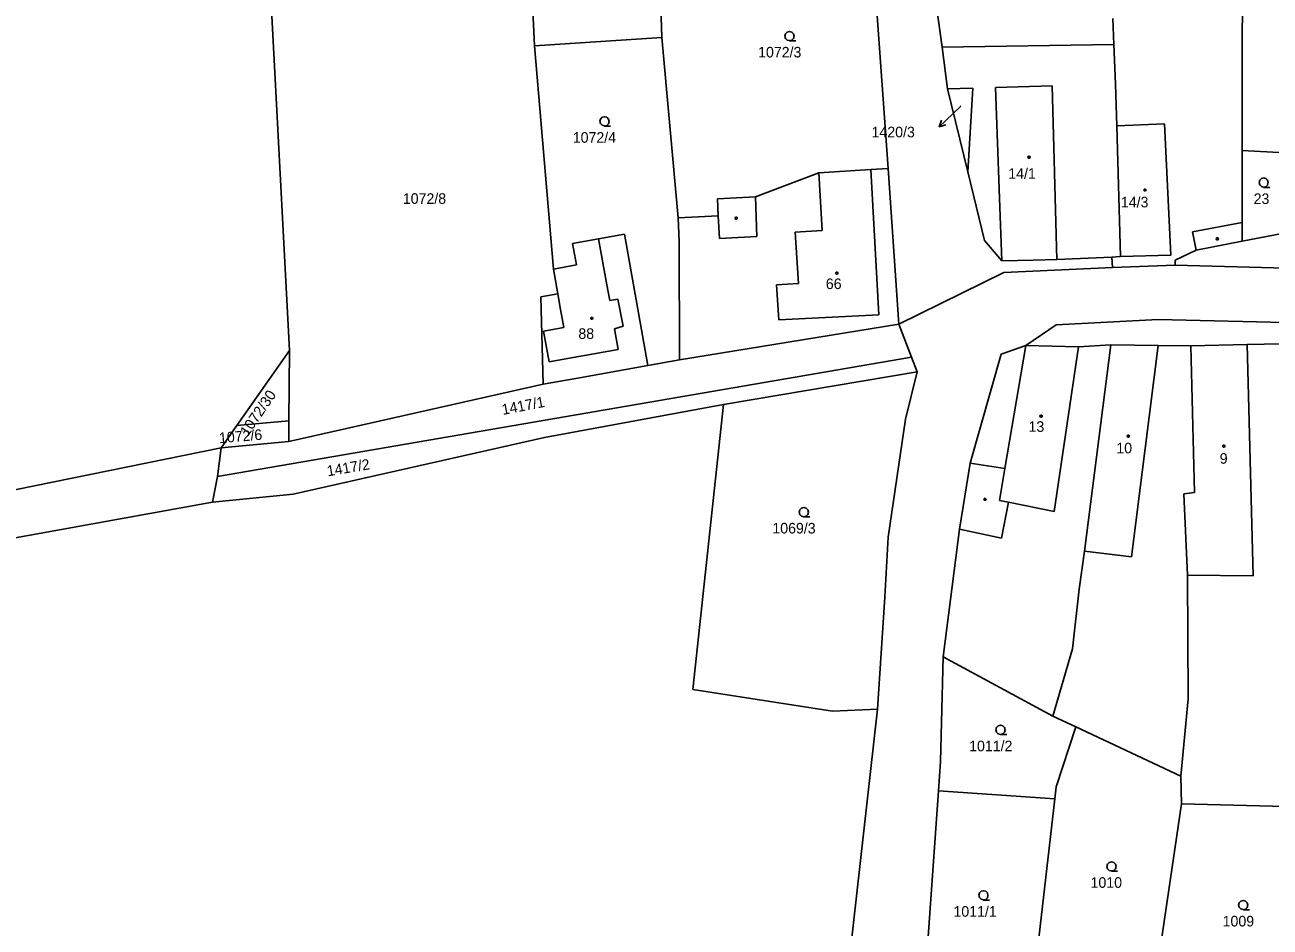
# Model space of a CAD drawing. Extents: x -850689 to -847910, y -1058374 to -1054747.
# Drawn here: x -849716.8 to -849516.8, y -1056444.2 to -1056299.3 of the extents above; entities that cross this region are included whole.
import ezdxf

# ---------------------------------------------------------------- set-up
doc = ezdxf.new("R2010")
doc.units = 0
for name, color, linetype in [('KN_HRANICE', 7, 'Continuous'), ('KN_KULTURY', 7, 'Continuous'), ('KN_PARCELY', 7, 'Continuous'), ('KN_SLUCKY', 7, 'Continuous'), ('KN_STAVEBNI', 7, 'Continuous')]:
    doc.layers.add(name, color=color, linetype=linetype)

# ---------------------------------------------------------------- blocks, each defined once
blk = doc.blocks.new('304')
blk.add_lwpolyline([(0, 0), (-0.38, 0.1), (-0.65, 0.37), (-0.75, 0.74), (-0.65, 1.11), (-0.38, 1.38), (-0.01, 1.48), (0.36, 1.38), (0.63, 1.11), (0.73, 0.73), (0.63, 0.35), (0.36, 0.08), (-0.02, -0.02), (0.98, -0.02)])
blk = doc.blocks.new('10292')
blk.add_line((0, 3), (0, 0))
blk.add_lwpolyline([(-0.5, 2), (0, 3), (0.5, 2)])
blk = doc.blocks.new('402')
blk.add_lwpolyline([(0.09, 0.15), (0.18, 0), (0.09, -0.15), (-0.09, -0.15), (-0.18, 0), (-0.09, 0.15), (0.09, 0.15)])

msp = doc.modelspace()

# ---------------------------------------------------------------- linework, layer by layer
at = {"layer": 'KN_HRANICE'}
for p, q in [((-849614.51, -1056301.38), (-849615.36, -1056276.4)), ((-849572.59, -1056279.79), (-849569.5, -1056302.91)), ((-849674.3, -1056351.59), (-849678, -1056281.13)), ((-849578.15, -1056322.42), (-849580.33, -1056292.14)), ((-849634.92, -1056302.69), (-849635.4, -1056293.21)), ((-849541.91, -1056302.5), (-849542.09, -1056298.32)), ((-849521.32, -1056300.37), (-849521.24, -1056297.73)), ((-849521.32, -1056319.52), (-849521.32, -1056300.37)), ((-849634.92, -1056302.69), (-849614.51, -1056301.38)), ((-849611.88, -1056330.31), (-849614.51, -1056301.38)), ((-849569.5, -1056302.91), (-849541.91, -1056302.5)), ((-849541.64, -1056308.88), (-849541.91, -1056302.5)), ((-849631.91, -1056338.54), (-849634.92, -1056302.69)), ((-849569.5, -1056302.91), (-849568.61, -1056309.6)), ((-849568.61, -1056309.6), (-849564.57, -1056309.49)), ((-849568.61, -1056309.6), (-849565.38, -1056322.92)), ((-849565.38, -1056322.92), (-849564.57, -1056309.49)), ((-849541.64, -1056308.88), (-849541.45, -1056315.57)), ((-849541.45, -1056315.57), (-849540.85, -1056336.53)), ((-849521.32, -1056331.05), (-849521.32, -1056319.52)), ((-849512.43, -1056319.98), (-849521.32, -1056319.52)), ((-849580.93, -1056322.58), (-849589.28, -1056323.07)), ((-849578.15, -1056322.42), (-849580.93, -1056322.58)), ((-849576.45, -1056347.39), (-849578.15, -1056322.42)), ((-849589.28, -1056323.07), (-849599.48, -1056326.92)), ((-849565.38, -1056322.92), (-849562.7, -1056333.97)), ((-849605.58, -1056327.27), (-849599.48, -1056326.92)), ((-849605.43, -1056329.98), (-849605.58, -1056327.27)), ((-849611.88, -1056330.31), (-849605.43, -1056329.98)), ((-849611.73, -1056334.13), (-849611.88, -1056330.31)), ((-849521.3, -1056334.07), (-849521.32, -1056331.05)), ((-849624.66, -1056333.71), (-849628.83, -1056334.46)), ((-849628.83, -1056334.46), (-849628.22, -1056337.88)), ((-849620.5, -1056332.96), (-849624.66, -1056333.71)), ((-849616.72, -1056354), (-849620.5, -1056332.96)), ((-849611.73, -1056334.13), (-849611.68, -1056353.09)), ((-849559.9, -1056337.24), (-849562.7, -1056333.97)), ((-849521.3, -1056334.07), (-849528.68, -1056335.48)), ((-849514.89, -1056332.85), (-849521.3, -1056334.07)), ((-849551.04, -1056336.99), (-849542.24, -1056336.61)), ((-849542.24, -1056336.61), (-849540.85, -1056336.53)), ((-849542.24, -1056336.61), (-849542.14, -1056338.3)), ((-849532.07, -1056337.11), (-849528.68, -1056335.48)), ((-849628.22, -1056337.88), (-849631.91, -1056338.54)), ((-849631.91, -1056338.54), (-849631.2, -1056342.49)), ((-849554.88, -1056337.1), (-849559.9, -1056337.24)), ((-849559.57, -1056339.1), (-849542.14, -1056338.3)), ((-849551.04, -1056336.99), (-849554.88, -1056337.1)), ((-849542.14, -1056338.3), (-849532.06, -1056337.93)), ((-849532.07, -1056337.11), (-849532.06, -1056337.93)), ((-849406.11, -1056341.28), (-849532.06, -1056337.93)), ((-849576.45, -1056347.39), (-849559.57, -1056339.1)), ((-849633.92, -1056342.98), (-849631.2, -1056342.49)), ((-849633.92, -1056342.98), (-849633.57, -1056357.04)), ((-849534.81, -1056346.62), (-849551.16, -1056347.5)), ((-849534.81, -1056346.62), (-849457.69, -1056348.54)), ((-849611.68, -1056353.09), (-849576.45, -1056347.39)), ((-849576.45, -1056347.39), (-849574.4, -1056352.7)), ((-849556.04, -1056350.8), (-849551.16, -1056347.5)), ((-849520.48, -1056350.65), (-849500.05, -1056350.21)), ((-849682.76, -1056363.66), (-849674.3, -1056351.59)), ((-849674.39, -1056362.91), (-849674.3, -1056351.59)), ((-849564.99, -1056369.69), (-849560.02, -1056352.2)), ((-849560.02, -1056352.2), (-849556.04, -1056350.8)), ((-849556.04, -1056350.8), (-849547.59, -1056351.01)), ((-849547.59, -1056351.01), (-849542.41, -1056350.72)), ((-849546.62, -1056383.82), (-849542.41, -1056350.72)), ((-849542.41, -1056350.72), (-849534.78, -1056350.83)), ((-849534.78, -1056350.83), (-849529.54, -1056350.88)), ((-849529.54, -1056350.88), (-849520.48, -1056350.65)), ((-849529.54, -1056350.88), (-849528.97, -1056374.41)), ((-849685.84, -1056371.84), (-849574.4, -1056352.7)), ((-849628.29, -1056356.09), (-849616.72, -1056354)), ((-849616.72, -1056354), (-849611.68, -1056353.09)), ((-849574.4, -1056352.7), (-849573.5, -1056355.04)), ((-849633.57, -1056357.04), (-849628.29, -1056356.09)), ((-849573.5, -1056355.04), (-849604.58, -1056360.3)), ((-849573.5, -1056355.04), (-849575.39, -1056362.66)), ((-849674.41, -1056366.2), (-849633.57, -1056357.04)), ((-849633.36, -1056365.59), (-849604.58, -1056360.3)), ((-849604.58, -1056360.3), (-849609.54, -1056406.05)), ((-849685.27, -1056367.24), (-849682.76, -1056363.66)), ((-849682.76, -1056363.66), (-849674.39, -1056362.91)), ((-849674.41, -1056366.2), (-849674.39, -1056362.91)), ((-849578.13, -1056381.59), (-849575.39, -1056362.66)), ((-849674.41, -1056366.2), (-849685.27, -1056367.24)), ((-849673.7, -1056374.66), (-849633.36, -1056365.59)), ((-849685.27, -1056367.24), (-849734.06, -1056377.17)), ((-849685.27, -1056367.24), (-849685.84, -1056371.84)), ((-849566.68, -1056380.28), (-849564.99, -1056369.69)), ((-849686.68, -1056375.97), (-849685.84, -1056371.84)), ((-849528.97, -1056374.41), (-849530.67, -1056374.61)), ((-849530.67, -1056374.61), (-849530.07, -1056387.67)), ((-849876.14, -1056410.04), (-849686.68, -1056375.97)), ((-849686.68, -1056375.97), (-849673.7, -1056374.66)), ((-849566.68, -1056380.28), (-849569.32, -1056400.81)), ((-849578.69, -1056391.21), (-849578.13, -1056381.59)), ((-849547.5, -1056389.93), (-849546.62, -1056383.82)), ((-849530, -1056407.52), (-849530.07, -1056387.67)), ((-849548.57, -1056399.5), (-849547.5, -1056389.93)), ((-849579.89, -1056409.19), (-849578.69, -1056391.21)), ((-849551.71, -1056410.33), (-849548.57, -1056399.5)), ((-849569.73, -1056417.59), (-849569.32, -1056400.81)), ((-849569.32, -1056400.81), (-849551.71, -1056410.33)), ((-849609.54, -1056406.05), (-849587.11, -1056409.52)), ((-849530, -1056407.52), (-849531.15, -1056419.97)), ((-849587.11, -1056409.52), (-849579.89, -1056409.19)), ((-849585.31, -1056457.89), (-849579.89, -1056409.19)), ((-849551.71, -1056410.33), (-849548.04, -1056412.05)), ((-849551.15, -1056421.68), (-849548.04, -1056412.05)), ((-849548.04, -1056412.05), (-849531.15, -1056419.97)), ((-849570.06, -1056422.29), (-849569.73, -1056417.59)), ((-849531.15, -1056419.97), (-849531.06, -1056424.37)), ((-849572.24, -1056453.32), (-849570.06, -1056422.29)), ((-849551.37, -1056423.56), (-849570.06, -1056422.29)), ((-849551.15, -1056421.68), (-849551.37, -1056423.56)), ((-849551.37, -1056423.56), (-849555.21, -1056456.71)), ((-849531.06, -1056424.37), (-849536.26, -1056459.7)), ((-849507.03, -1056425.02), (-849531.06, -1056424.37))]:
    msp.add_line(p, q, dxfattribs=at)
at = {"layer": 'KN_PARCELY'}
msp.add_line((-849566.46, -1056312.38), (-849567.77, -1056313.63), dxfattribs=at)
at = {"layer": 'KN_SLUCKY'}
for p, q in [((-849560.9, -1056309.39), (-849551.84, -1056309.15)), ((-849560.26, -1056327.16), (-849560.9, -1056309.39)), ((-849551.84, -1056309.15), (-849551.04, -1056336.99)), ((-849541.45, -1056315.57), (-849533.76, -1056315.2)), ((-849532.75, -1056336.3), (-849533.76, -1056315.2)), ((-849579.67, -1056345.88), (-849580.93, -1056322.58)), ((-849589.28, -1056323.07), (-849588.73, -1056332.37)), ((-849599.48, -1056326.92), (-849599.25, -1056333.3)), ((-849559.9, -1056337.24), (-849560.26, -1056327.16)), ((-849605.22, -1056333.64), (-849605.43, -1056329.98)), ((-849588.73, -1056332.37), (-849593.06, -1056332.62)), ((-849593.06, -1056332.62), (-849592.57, -1056340.88)), ((-849529.28, -1056332.55), (-849521.32, -1056331.05)), ((-849528.68, -1056335.48), (-849529.28, -1056332.55)), ((-849623.34, -1056341.09), (-849624.66, -1056333.71)), ((-849605.22, -1056333.64), (-849599.25, -1056333.3)), ((-849532.75, -1056336.3), (-849540.85, -1056336.53)), ((-849631.2, -1056342.49), (-849630.75, -1056345.04)), ((-849622.85, -1056343.61), (-849623.34, -1056341.09)), ((-849592.57, -1056340.88), (-849596.08, -1056341.09)), ((-849596.08, -1056341.09), (-849595.73, -1056346.69)), ((-849621.57, -1056343.36), (-849622.85, -1056343.61)), ((-849620.72, -1056347.73), (-849621.57, -1056343.36)), ((-849630.75, -1056345.04), (-849630.22, -1056347.9)), ((-849595.73, -1056346.69), (-849579.67, -1056345.88)), ((-849630.22, -1056347.9), (-849633.49, -1056348.51)), ((-849633.49, -1056348.51), (-849632.58, -1056353.43)), ((-849622.1, -1056348.13), (-849620.72, -1056347.73)), ((-849621.5, -1056351.43), (-849622.1, -1056348.13)), ((-849629.33, -1056352.84), (-849621.5, -1056351.43)), ((-849556.04, -1056350.8), (-849559.41, -1056370.58)), ((-849547.59, -1056351.01), (-849551.51, -1056377.44)), ((-849539.06, -1056384.74), (-849534.78, -1056350.83)), ((-849519.54, -1056387.79), (-849520.48, -1056350.65)), ((-849632.58, -1056353.43), (-849629.33, -1056352.84)), ((-849559.41, -1056370.58), (-849564.99, -1056369.69)), ((-849559.41, -1056370.58), (-849560.28, -1056375.69)), ((-849558.83, -1056375.98), (-849560.28, -1056375.69)), ((-849558.83, -1056375.98), (-849559.93, -1056381.74)), ((-849551.51, -1056377.44), (-849558.83, -1056375.98)), ((-849559.93, -1056381.74), (-849566.68, -1056380.28)), ((-849546.62, -1056383.82), (-849539.06, -1056384.74)), ((-849530.07, -1056387.67), (-849519.54, -1056387.79))]:
    msp.add_line(p, q, dxfattribs=at)
at = {"layer": 'KN_STAVEBNI'}
for p, q in [((-849560.9, -1056309.39), (-849551.84, -1056309.15)), ((-849560.26, -1056327.16), (-849560.9, -1056309.39)), ((-849551.84, -1056309.15), (-849551.04, -1056336.99)), ((-849541.45, -1056315.57), (-849533.76, -1056315.2)), ((-849541.45, -1056315.57), (-849540.85, -1056336.53)), ((-849532.75, -1056336.3), (-849533.76, -1056315.2)), ((-849580.93, -1056322.58), (-849589.28, -1056323.07)), ((-849579.67, -1056345.88), (-849580.93, -1056322.58)), ((-849589.28, -1056323.07), (-849588.73, -1056332.37)), ((-849559.9, -1056337.24), (-849560.26, -1056327.16)), ((-849588.73, -1056332.37), (-849593.06, -1056332.62)), ((-849593.06, -1056332.62), (-849592.57, -1056340.88)), ((-849624.66, -1056333.71), (-849628.83, -1056334.46)), ((-849628.83, -1056334.46), (-849628.22, -1056337.88)), ((-849623.34, -1056341.09), (-849624.66, -1056333.71)), ((-849532.75, -1056336.3), (-849540.85, -1056336.53)), ((-849628.22, -1056337.88), (-849631.91, -1056338.54)), ((-849631.91, -1056338.54), (-849631.2, -1056342.49)), ((-849554.88, -1056337.1), (-849559.9, -1056337.24)), ((-849551.04, -1056336.99), (-849554.88, -1056337.1)), ((-849631.2, -1056342.49), (-849630.75, -1056345.04)), ((-849622.85, -1056343.61), (-849623.34, -1056341.09)), ((-849592.57, -1056340.88), (-849596.08, -1056341.09)), ((-849596.08, -1056341.09), (-849595.73, -1056346.69)), ((-849621.57, -1056343.36), (-849622.85, -1056343.61)), ((-849620.72, -1056347.73), (-849621.57, -1056343.36)), ((-849630.75, -1056345.04), (-849630.22, -1056347.9)), ((-849595.73, -1056346.69), (-849579.67, -1056345.88)), ((-849630.22, -1056347.9), (-849633.49, -1056348.51)), ((-849633.49, -1056348.51), (-849632.58, -1056353.43)), ((-849622.1, -1056348.13), (-849620.72, -1056347.73)), ((-849621.5, -1056351.43), (-849622.1, -1056348.13)), ((-849629.33, -1056352.84), (-849621.5, -1056351.43)), ((-849556.04, -1056350.8), (-849559.41, -1056370.58)), ((-849556.04, -1056350.8), (-849547.59, -1056351.01)), ((-849547.59, -1056351.01), (-849551.51, -1056377.44)), ((-849546.62, -1056383.82), (-849542.41, -1056350.72)), ((-849542.41, -1056350.72), (-849534.78, -1056350.83)), ((-849539.06, -1056384.74), (-849534.78, -1056350.83)), ((-849529.54, -1056350.88), (-849520.48, -1056350.65)), ((-849529.54, -1056350.88), (-849528.97, -1056374.41)), ((-849519.54, -1056387.79), (-849520.48, -1056350.65)), ((-849632.58, -1056353.43), (-849629.33, -1056352.84)), ((-849559.41, -1056370.58), (-849560.28, -1056375.69)), ((-849528.97, -1056374.41), (-849530.67, -1056374.61)), ((-849530.67, -1056374.61), (-849530.07, -1056387.67)), ((-849558.83, -1056375.98), (-849560.28, -1056375.69)), ((-849551.51, -1056377.44), (-849558.83, -1056375.98)), ((-849546.62, -1056383.82), (-849539.06, -1056384.74)), ((-849530.07, -1056387.67), (-849519.54, -1056387.79))]:
    msp.add_line(p, q, dxfattribs=at)

# ---------------------------------------------------------------- block references
at = {"layer": 'KN_KULTURY'}
for name, p in [('304', (-849593.98, -1056301.87)), ('304', (-849623.7, -1056315.56)), ('402', (-849555.53, -1056320.57)), ('304', (-849517.84, -1056325.4)), ('402', (-849536.92, -1056325.84)), ('402', (-849602.56, -1056330.38)), ('402', (-849525.29, -1056333.7)), ('402', (-849586.39, -1056339.2)), ('402', (-849625.74, -1056346.44)), ('402', (-849553.59, -1056362.16)), ('402', (-849539.6, -1056365.36)), ('402', (-849524.25, -1056366.97)), ('402', (-849562.61, -1056375.5)), ('304', (-849591.69, -1056378.29)), ('304', (-849560.09, -1056413.25)), ('304', (-849542.29, -1056435.17)), ('304', (-849562.85, -1056439.81)), ('304', (-849521.12, -1056441.37))]:
    msp.add_blockref(name, p, dxfattribs=at)
at = {"layer": 'KN_PARCELY', "rotation": 133.499166}
msp.add_blockref('10292', (-849567.77, -1056313.63), dxfattribs=at)

# ---------------------------------------------------------------- texts
at = {"layer": 'KN_PARCELY'}
for s, p in [('1072/3', (-849599.04, -1056304.57)), ('1072/4', (-849628.8, -1056318.26)), ('1420/3', (-849580.82, -1056317.39)), ('14/1', (-849558.86, -1056324.05)), ('1072/8', (-849656.09, -1056328.07)), ('23', (-849519.46, -1056328.1)), ('14/3', (-849540.78, -1056328.64)), ('66', (-849588.16, -1056341.75)), ('88', (-849627.9, -1056349.75)), ('13', (-849555.61, -1056364.67)), ('10', (-849541.51, -1056368.12)), ('9', (-849524.91, -1056369.79)), ('1069/3', (-849596.75, -1056380.99)), ('1011/2', (-849565.15, -1056415.95)), ('1010', (-849545.65, -1056437.87)), ('1011/1', (-849567.67, -1056442.51)), ('1009', (-849524.44, -1056444.07))]:
    msp.add_text(s, height=1.7, dxfattribs=at).set_placement(p)
for s, height, rotation, p in [('1420/3', 0.1, 90.642, (-849566.46, -1056312.63)), ('1072/30', 1.7, 55.691, (-849680.98, -1056365.5)), ('1417/1', 1.7, 10.886, (-849640.03, -1056361.96)), ('1072/6', 1.7, 4.813, (-849685.54, -1056366.51)), ('1417/2', 1.7, 9.568, (-849668.14, -1056371.82))]:
    msp.add_text(s, height=height, rotation=rotation, dxfattribs=at).set_placement(p)

doc.saveas('drawing.dxf')
